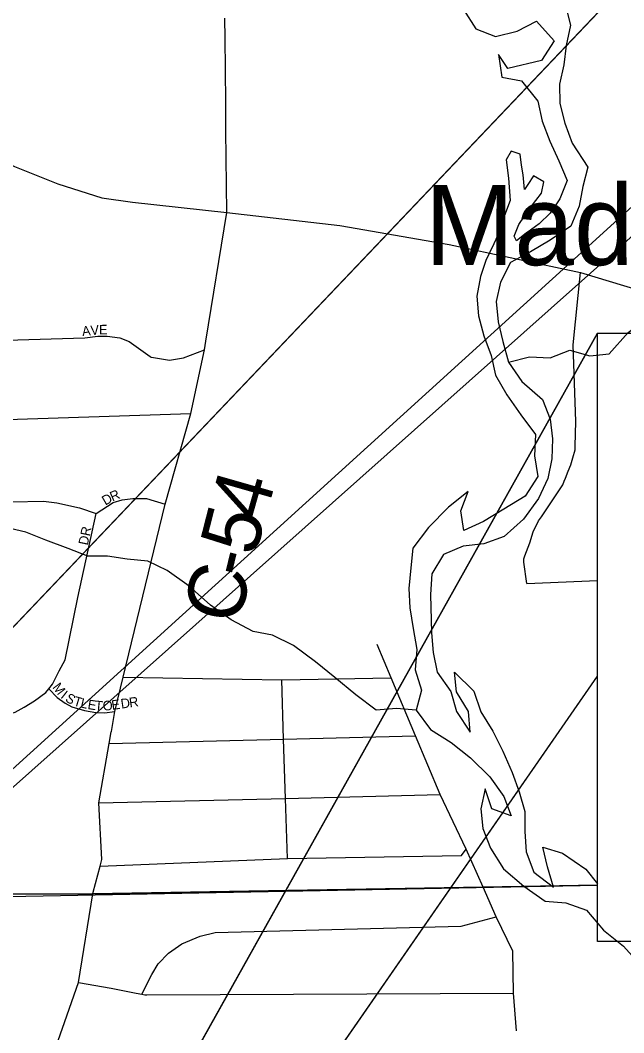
# Model space of a CAD drawing. Extents: x -37878.7 to -37844.7, y -19791.4 to -19769.4.
# Drawn here: x -37872.836 to -37872.242, y -19774.18 to -19773.183 of the extents above; entities that cross this region are included whole.
import ezdxf

# ---------------------------------------------------------------- set-up
doc = ezdxf.new("R2010")
doc.units = 0
for name, color, linetype in [('GM_X_City_Street', 7, 'Continuous'), ('GM_X_County_Road', 7, 'Continuous'), ('GM_X_County_Road_Text', 7, 'Continuous'), ('GM_X_Major_River', 7, 'Continuous'), ('GM_X_Minor_River', 7, 'Continuous'), ('GM_X_Section', 7, 'Continuous'), ('GM_X_Township', 7, 'Continuous'), ('GM_X_Township_Subdivision', 7, 'Continuous'), ('GM_X_Township_Subdivision_Text', 7, 'Continuous'), ('GM_X_Unincorporated_Text', 7, 'Continuous'), ('GM_X_US_Route', 7, 'Continuous'), ('TX_P_1', 7, 'Continuous')]:
    doc.layers.add(name, color=color, linetype=linetype)

msp = doc.modelspace()

# ---------------------------------------------------------------- linework, layer by layer
at = {"layer": 'GM_X_City_Street'}
for points in [[(-37872.63377, -19773.23108), (-37872.63406, -19773.20087)], [(-37872.63243, -19773.37204), (-37872.63319, -19773.29149)], [(-37872.653, -19773.49882), (-37872.63243, -19773.37204)], [(-37872.33723, -19773.73716), (-37872.34, -19773.71637), (-37872.34016, -19773.71316), (-37872.33913, -19773.71015), (-37872.33419, -19773.69718), (-37872.33083, -19773.68634), (-37872.32565, -19773.67565), (-37872.32264, -19773.67167), (-37872.31152, -19773.65492), (-37872.30181, -19773.64013), (-37872.30046, -19773.63665), (-37872.29904, -19773.63374), (-37872.29645, -19773.62685), (-37872.29385, -19773.62063), (-37872.29179, -19773.61357), (-37872.28972, -19773.60564), (-37872.28963, -19773.60207), (-37872.28903, -19773.57775), (-37872.29151, -19773.50228), (-37872.28436, -19773.43116)], [(-37872.33723, -19773.73716), (-37872.2676, -19773.73425)], [(-37872.34746, -19774.17759), (-37872.35039, -19774.14049), (-37872.35081, -19774.09913), (-37872.36725, -19774.06536), (-37872.38016, -19774.03604), (-37872.39675, -19773.9988), (-37872.42248, -19773.94515), (-37872.44679, -19773.88713), (-37872.47064, -19773.83021), (-37872.48437, -19773.79745)], [(-37872.73433, -19773.82939), (-37872.57824, -19773.83218), (-37872.47064, -19773.83021)], [(-37872.57271, -19774.00814), (-37872.57471, -19773.94883), (-37872.57648, -19773.89042), (-37872.57824, -19773.83218)], [(-37872.76372, -19774.04126), (-37872.75712, -19774.01537), (-37872.75548, -19774.00892), (-37872.75816, -19773.95326), (-37872.74801, -19773.89477), (-37872.74599, -19773.88314), (-37872.74597, -19773.88304)], [(-37872.74801, -19773.89477), (-37872.57648, -19773.89042), (-37872.44679, -19773.88713)], [(-37872.75816, -19773.95326), (-37872.57471, -19773.94883), (-37872.42248, -19773.94515)], [(-37872.75712, -19774.01537), (-37872.57271, -19774.00814), (-37872.40154, -19774.00507), (-37872.39675, -19773.9988)], [(-37872.92626, -19774.82475), (-37872.92075, -19774.80767), (-37872.89107, -19774.66033), (-37872.88608, -19774.59166), (-37872.87809, -19774.55541), (-37872.84947, -19774.41365), (-37872.84795, -19774.40606), (-37872.83431, -19774.33973), (-37872.82299, -19774.28465), (-37872.80971, -19774.22004), (-37872.7782, -19774.13007), (-37872.76408, -19774.04266), (-37872.76372, -19774.04126)], [(-37872.85505, -19774.04299), (-37872.83024, -19774.0429)], [(-37872.83024, -19774.0429), (-37872.76408, -19774.04266)], [(-37872.71594, -19774.14159), (-37872.70605, -19774.12221), (-37872.7, -19774.11172), (-37872.68978, -19774.10108), (-37872.67648, -19774.09184), (-37872.65857, -19774.08432), (-37872.64391, -19774.08072), (-37872.40181, -19774.0745), (-37872.36725, -19774.06536)], [(-37872.7782, -19774.13007), (-37872.74612, -19774.1355), (-37872.72168, -19774.14043), (-37872.71594, -19774.14159), (-37872.71287, -19774.14221), (-37872.71109, -19774.1422)], [(-37872.71109, -19774.1422), (-37872.35039, -19774.14049)]]:
    msp.add_lwpolyline(points, dxfattribs=at)
at = {"layer": 'GM_X_County_Road'}
for points in [[(-37872.63406, -19773.20087), (-37872.63426, -19773.18073)], [(-37872.63319, -19773.29149), (-37872.63345, -19773.26438), (-37872.63377, -19773.23108)], [(-37872.74597, -19773.88304), (-37872.74255, -19773.86329), (-37872.73433, -19773.82939), (-37872.69308, -19773.65916), (-37872.66782, -19773.57005), (-37872.65437, -19773.50725), (-37872.653, -19773.49882)]]:
    msp.add_lwpolyline(points, dxfattribs=at)
at = {"layer": 'GM_X_Major_River'}
for points in [[(-37872.2992, -19773.16821), (-37872.29425, -19773.18785), (-37872.29838, -19773.20767), (-37872.30064, -19773.2267), (-37872.30517, -19773.24578), (-37872.30477, -19773.26475), (-37872.29983, -19773.28401), (-37872.29259, -19773.30397), (-37872.27733, -19773.32756), (-37872.28223, -19773.34665), (-37872.28562, -19773.3657), (-37872.29392, -19773.38562), (-37872.31409, -19773.39933), (-37872.33356, -19773.41076), (-37872.35341, -19773.42143), (-37872.36324, -19773.44062), (-37872.36739, -19773.45969), (-37872.36546, -19773.47977), (-37872.36089, -19773.49903), (-37872.35516, -19773.51941), (-37872.34226, -19773.5385), (-37872.32181, -19773.55628), (-37872.31421, -19773.57548), (-37872.31192, -19773.59479), (-37872.31264, -19773.61454), (-37872.3164, -19773.63398), (-37872.32585, -19773.65355), (-37872.34057, -19773.67398), (-37872.35954, -19773.69109), (-37872.37947, -19773.69834), (-37872.39987, -19773.70068), (-37872.41903, -19773.70868), (-37872.43075, -19773.72791), (-37872.43185, -19773.74805), (-37872.43105, -19773.78599), (-37872.42951, -19773.80532), (-37872.42532, -19773.82459), (-37872.41204, -19773.84367), (-37872.40633, -19773.86328), (-37872.39303, -19773.8835), (-37872.39458, -19773.86341), (-37872.40636, -19773.84392), (-37872.40827, -19773.82461), (-37872.38932, -19773.84318), (-37872.38246, -19773.86353), (-37872.3707, -19773.88264), (-37872.36082, -19773.90217), (-37872.35166, -19773.92323), (-37872.34482, -19773.94244), (-37872.33912, -19773.96168), (-37872.33908, -19773.98142), (-37872.3379, -19774.00151), (-37872.33029, -19774.02147), (-37872.31104, -19774.03624), (-37872.31676, -19774.01624), (-37872.32133, -19773.99698), (-37872.30227, -19774.00265), (-37872.27921, -19774.01848), (-37872.2676, -19774.03304)], [(-37872.39951, -19773.17225), (-37872.38737, -19773.19135), (-37872.36789, -19773.19891), (-37872.34679, -19773.19352), (-37872.32768, -19773.18362), (-37872.31023, -19773.20299), (-37872.3227, -19773.22262), (-37872.35604, -19773.2303), (-37872.36505, -19773.21642), (-37872.36176, -19773.23901), (-37872.34237, -19773.2424), (-37872.32641, -19773.26256), (-37872.32221, -19773.28221), (-37872.31461, -19773.30178), (-37872.30587, -19773.32134), (-37872.29751, -19773.34052)], [(-37872.29751, -19773.34052), (-37872.30472, -19773.35852), (-37872.31427, -19773.37276), (-37872.32504, -19773.38325), (-37872.33959, -19773.3938), (-37872.34742, -19773.40005), (-37872.34979, -19773.39554), (-37872.3451, -19773.38405), (-37872.33408, -19773.36749), (-37872.32263, -19773.3532), (-37872.3206, -19773.34177), (-37872.33057, -19773.33591), (-37872.33607, -19773.34438), (-37872.33938, -19773.34939), (-37872.34082, -19773.33499), (-37872.34253, -19773.32554), (-37872.34389, -19773.31456), (-37872.35267, -19773.31171), (-37872.35741, -19773.32016), (-37872.35514, -19773.33834), (-37872.35355, -19773.36032), (-37872.36001, -19773.37754), (-37872.36246, -19773.38708), (-37872.36971, -19773.4028), (-37872.3777, -19773.41929), (-37872.38268, -19773.43497)], [(-37872.38268, -19773.43497), (-37872.38644, -19773.4544), (-37872.3849, -19773.47373), (-37872.37957, -19773.49336), (-37872.37234, -19773.51294), (-37872.36815, -19773.53221), (-37872.35676, -19773.55171), (-37872.3431, -19773.57116), (-37872.32867, -19773.59059), (-37872.32975, -19773.61149), (-37872.3263, -19773.63192), (-37872.33878, -19773.65116), (-37872.35972, -19773.66414), (-37872.37992, -19773.67634), (-37872.39906, -19773.6851), (-37872.40212, -19773.6658), (-37872.39494, -19773.64667), (-37872.41431, -19773.66227), (-37872.43398, -19773.68205), (-37872.44946, -19773.7025), (-37872.45133, -19773.7219), (-37872.45318, -19773.74205), (-37872.4524, -19773.7614), (-37872.44895, -19773.78144), (-37872.44549, -19773.80224), (-37872.44696, -19773.8224), (-37872.44086, -19773.84238), (-37872.44614, -19773.86186), (-37872.4321, -19773.88092), (-37872.41176, -19773.89377), (-37872.3925, -19773.90892), (-37872.37355, -19773.92749), (-37872.35988, -19773.94694), (-37872.35266, -19773.96614), (-37872.37175, -19773.95896), (-37872.37822, -19773.93936), (-37872.38236, -19773.95919), (-37872.38044, -19773.97851), (-37872.37284, -19773.9977), (-37872.36028, -19774.01831), (-37872.34023, -19774.03534), (-37872.31908, -19774.05007), (-37872.29898, -19774.05154), (-37872.27837, -19774.0587), (-37872.26166, -19774.07845), (-37872.24201, -19774.09436), (-37872.22456, -19774.11372)]]:
    msp.add_lwpolyline(points, dxfattribs=at)
at = {"layer": 'GM_X_Minor_River'}
for points in [[(-37872.35516, -19773.51941), (-37872.33444, -19773.51403), (-37872.31434, -19773.51512), (-37872.2948, -19773.50749), (-37872.27536, -19773.51315), (-37872.25608, -19773.51122), (-37872.23757, -19773.49033), (-37872.21854, -19773.47626), (-37872.20796, -19773.45667), (-37872.18884, -19773.44715), (-37872.16734, -19773.44252), (-37872.14799, -19773.444), (-37872.12862, -19773.44663), (-37872.10954, -19773.45305), (-37872.09038, -19773.46327), (-37872.07128, -19773.47084), (-37872.05182, -19773.47763), (-37872.0327, -19773.48634), (-37872.02236, -19773.49075)], [(-37872.44614, -19773.86186), (-37872.46549, -19773.86037), (-37872.48554, -19773.86194), (-37872.50555, -19773.8468), (-37872.52599, -19773.82978), (-37872.54525, -19773.81424), (-37872.5668, -19773.79838), (-37872.58747, -19773.78819), (-37872.60649, -19773.78442), (-37872.62794, -19773.77311), (-37872.64832, -19773.75874), (-37872.66955, -19773.73984), (-37872.69108, -19773.72436), (-37872.71022, -19773.71527), (-37872.73033, -19773.71343), (-37872.74972, -19773.71042), (-37872.76904, -19773.71045), (-37872.78851, -19773.7029), (-37872.81028, -19773.69463), (-37872.83014, -19773.68671), (-37872.85108, -19773.68184)]]:
    msp.add_lwpolyline(points, dxfattribs=at)
at = {"layer": 'GM_X_Section'}
msp.add_lwpolyline([(-37872.18692, -19774.08978), (-37872.17025, -19774.67952), (-37872.58024, -19774.69042), (-37872.96634, -19774.70069), (-37873.29687, -19774.70587), (-37873.69019, -19774.71163), (-37873.75987, -19774.71265), (-37873.7756, -19774.06152), (-37873.05223, -19774.04922), (-37872.2676, -19774.03426)], dxfattribs=at)
at = {"layer": 'GM_X_Township'}
for points in [[(-37872.2676, -19774.0341), (-37872.38016, -19774.03604), (-37872.76408, -19774.04266), (-37872.85506, -19774.043), (-37872.94239, -19774.04564), (-37873.07009, -19774.04829), (-37873.08696, -19774.04763), (-37873.22557, -19774.05027), (-37873.2959, -19774.0514), (-37873.32101, -19774.05101), (-37873.43906, -19774.05375), (-37873.48951, -19774.05375), (-37873.76133, -19774.06615), (-37873.82094, -19774.06728), (-37873.90676, -19774.06892), (-37874.01664, -19774.06271), (-37874.41791, -19774.07867), (-37875.13726, -19774.08233), (-37875.16478, -19772.49865)], [(-37875.12559, -19774.70629), (-37875.12978, -19774.45993), (-37875.13234, -19774.33027), (-37875.13726, -19774.08233), (-37874.41791, -19774.07867), (-37874.01664, -19774.06271), (-37873.90676, -19774.06892), (-37873.82094, -19774.06728), (-37873.76133, -19774.06615), (-37873.48951, -19774.05375), (-37873.43906, -19774.05375), (-37873.32101, -19774.05101), (-37873.2959, -19774.0514), (-37873.22557, -19774.05027), (-37873.08696, -19774.04763), (-37873.07009, -19774.04829), (-37872.94239, -19774.04564), (-37872.85506, -19774.043), (-37872.76408, -19774.04266), (-37872.38016, -19774.03604), (-37872.2676, -19774.0341)]]:
    msp.add_lwpolyline(points, dxfattribs=at)
at = {"layer": 'GM_X_Township_Subdivision'}
for points in [[(-37873.09997, -19773.50951), (-37872.93733, -19773.50051), (-37872.77219, -19773.49563), (-37872.75928, -19773.4937), (-37872.75012, -19773.4937), (-37872.73763, -19773.49553), (-37872.72831, -19773.49901), (-37872.70769, -19773.51396), (-37872.7068, -19773.51452), (-37872.70457, -19773.51487), (-37872.68886, -19773.51729), (-37872.67489, -19773.51509), (-37872.65437, -19773.50725)], [(-37873.60284, -19773.58861), (-37873.23709, -19773.58883), (-37873.09979, -19773.58392), (-37872.66782, -19773.57005)], [(-37873.09972, -19773.66174), (-37873.03288, -19773.66045), (-37872.96112, -19773.65906), (-37872.84377, -19773.6568), (-37872.81262, -19773.65632), (-37872.79973, -19773.65787), (-37872.77728, -19773.66267), (-37872.7609, -19773.66831), (-37872.74425, -19773.65764), (-37872.73528, -19773.65506), (-37872.72468, -19773.65374), (-37872.71123, -19773.65374), (-37872.69308, -19773.65916)], [(-37872.95562, -19773.87847), (-37872.9265, -19773.87569), (-37872.8836, -19773.87329), (-37872.85904, -19773.8691), (-37872.84072, -19773.86405), (-37872.83165, -19773.85896), (-37872.82149, -19773.85279), (-37872.81041, -19773.8446), (-37872.80738, -19773.84086), (-37872.80382, -19773.83646), (-37872.79719, -19773.82323), (-37872.79154, -19773.81228), (-37872.77885, -19773.75113), (-37872.7609, -19773.66831)], [(-37872.80738, -19773.84086), (-37872.79942, -19773.84949), (-37872.79148, -19773.85524), (-37872.78491, -19773.85857), (-37872.77249, -19773.86232), (-37872.76134, -19773.8642), (-37872.75263, -19773.86454), (-37872.74255, -19773.86329)]]:
    msp.add_lwpolyline(points, dxfattribs=at)
at = {"layer": 'GM_X_US_Route'}
for points in [[(-37872.94003, -19773.26856), (-37872.88901, -19773.30144), (-37872.84139, -19773.32688), (-37872.79877, -19773.34398), (-37872.7554, -19773.35776), (-37872.72529, -19773.36184), (-37872.63243, -19773.37204)], [(-37872.63243, -19773.37204), (-37872.52129, -19773.38503), (-37872.4135, -19773.40348), (-37872.28436, -19773.43116), (-37872.14337, -19773.47365), (-37872.13693, -19773.47559), (-37872.09168, -19773.49075)]]:
    msp.add_lwpolyline(points, dxfattribs=at)
at = {"layer": 'TX_P_1'}
for p, q in [((-37871.71882, -19772.5985), (-37873.82258, -19774.8103)), ((-37873.82258, -19774.8103), (-37871.71882, -19772.89801)), ((-37873.24554, -19775.24014), (-37872.2676, -19773.49075)), ((-37872.2676, -19773.49075), (-37870.28883, -19773.49075)), ((-37872.2676, -19774.08978), (-37872.2676, -19773.49075)), ((-37873.24554, -19775.24014), (-37872.2676, -19773.8285)), ((-37870.28883, -19774.08978), (-37872.2676, -19774.08978))]:
    msp.add_line(p, q, dxfattribs=at)
for points in [[(-37871.71882, -19772.5985), (-37873.82258, -19774.8103), (-37871.71882, -19772.93626)], [(-37872.2676, -19773.49075), (-37873.24554, -19775.24014), (-37872.2676, -19773.8285)]]:
    msp.add_lwpolyline(points, close=True, dxfattribs=at)

# ---------------------------------------------------------------- texts
at = {"layer": 'GM_X_County_Road_Text'}
for s, rotation, p in [('4', 74.10178, (-37872.59575, -19773.678)), ('5', 75.6703, (-37872.6043, -19773.71152)), ('-', 76.28748, (-37872.60979, -19773.73403)), ('C', 76.5161, (-37872.62066, -19773.77935))]:
    msp.add_text(s, height=0.05682, rotation=rotation, dxfattribs=at).set_placement(p)
at = {"layer": 'GM_X_Township_Subdivision_Text'}
for s, rotation, p in [('V', 4.71464, (-37872.76615, -19773.49287)), ('E', 0.87426, (-37872.75801, -19773.49219)), ('A', 6.21951, (-37872.77437, -19773.49377)), ('D', 30.19351, (-37872.75184, -19773.66073)), ('R', 23.59878, (-37872.7449, -19773.65667)), ('DR', 78.11713, (-37872.76924, -19773.70017)), ('M', 307.17771, (-37872.80436, -19773.83953)), ('I', 321.83763, (-37872.79647, -19773.84938)), ('S', 329.42031, (-37872.79206, -19773.85272)), ('T', 343.82047, (-37872.78394, -19773.85714)), ('L', 347.16562, (-37872.77696, -19773.85915)), ('E', 351.06991, (-37872.76976, -19773.86077)), ('E', 8.13829, (-37872.74516, -19773.8618)), ('D', 8.32339, (-37872.73605, -19773.86049)), ('R', 8.31657, (-37872.72781, -19773.85929)), ('T', 354.4725, (-37872.76257, -19773.86188)), ('O', 4.54677, (-37872.75412, -19773.86253))]:
    msp.add_text(s, height=0.00947, rotation=rotation, dxfattribs=at).set_placement(p)
at = {"layer": 'GM_X_Unincorporated_Text'}
msp.add_text('Madden Corners', height=0.0789769, rotation=0.00001, dxfattribs=at).set_placement((-37872.4375, -19773.42391))

doc.saveas('drawing.dxf')
